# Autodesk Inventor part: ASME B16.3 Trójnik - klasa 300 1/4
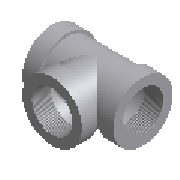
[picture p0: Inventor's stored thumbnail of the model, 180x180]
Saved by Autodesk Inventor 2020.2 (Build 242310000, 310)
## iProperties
Manager: www.cadconsulting.pl
Company: Fabian Stasiak CAD Consulting
Created: 2016-02
Part Number: ASME B16.3 Trójnik - klasa 300 1/4
Material: Żelazo, ciągliwe
Description: Trójnik
Document SubType Name: Modeling
Standard: ASME B16.3
Designer: F.Stasiak
Standard Revision: 2011
Standards Organization: ANSI
Language: pl-PL
Size Designation: 1/4
Categories: <MemberInstance><Categories><Category DisplayName="Rury cienko- i grubościenne" InternalName="4347fa0f-2144-441d-94cd-e3e15c92b736" Mnemonic="TUBEANDPIPE"><Cate
Density: 7.15 g/cm^3
Appearance: Częściowo polerowana
Catalog Web Link: www.expertbooks.pl
NAME: PIPING: ASME B16.3 Tee - Class 300
DATA: <meta><inlinegroups number="1" deflen="4.7752"></inlinegroups><connections number="3"></connections><angles><a>3.14159265358979</a><a>1.5707963267949</a></angle
IsCustomPart: 0
Author: F.Stasiak
Subject: Zbiór ćwiczeń. Autodesk Inventor 2020. Kurs Professional
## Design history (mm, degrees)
sketch "Sketch1"
  geometry: L1 (0, 11.811)-(9.652, 11.811); L2 (9.652, 11.811)-(9.652, 10.922); L3 (38.1, 10.922)-(38.1, 11.811); L4 (38.1, 11.811)-(47.752, 11.811); L5 (47.752, 11.811)-(47.752, 5.679); L6 (47.752, 5.679)-(47.752, 0); L7 (47.752, 0)-(0, 0); L8 (0, 0)-(0, 5.679); L9 (0, 5.679)-(10.922, 5.338); L10 (10.922, 5.338)-(10.922, 7.366); L11 (47.752, 5.679)-(36.83, 5.338); L12 (36.83, 5.338)-(36.83, 7.366); L13 (0, 5.679)-(0, 11.811); L14 (9.652, 11.811)-(23.876, 11.811); L15 (23.876, 11.811)-(38.1, 11.811); L16 (23.876, 11.811)-(23.876, 0); L17 (9.652, 10.922)-(23.876, 10.922); L18 (23.876, 10.922)-(38.1, 10.922); L19 (10.922, 7.366)-(23.876, 7.366); L20 (23.876, 7.366)-(36.83, 7.366)
  constraints: 40 end point, 5 perpendicular, 4 collinear, 3 parallel, 2 point on line, 1 horizontal, 1 midpoint, 8 other
  dimensions: "d0" = 11.35863 diameter of L8.end L7 (= MD); "d1" = 23.622 diameter of L1 L7 (= H); "d2" = 9.652 distance of L1.start L1.end (= E1); "d3" = 23.876 distance of L14.end L1.start (= A); "d4" = 10.922 horizontal distance of L9.end L8.end (= B); "d5" = 14.732 diameter of L19 L7 (= F1); "d6" = 3.556 distance between parallel lines of L19 L17 (= G); "d7" = 1.78991 deg angle of L7 L9
revolve "Revolve1" stored, may be unused: angle "d11" = 90 deg
workplane "Work Plane1"
sketch "Sketch2"
  geometry: L1 (0, 11.811)-(0, -11.811) reference; L2 (47.752, 11.811)-(47.752, -11.811) reference; L3 (47.752, 5.679)-(47.752, -5.679) reference; L4 (0, 0)-(47.752, 0); C1 r 5.679 at (23.876, 0); C2 r 10.922 at (23.876, 0); C3 r 11.811 at (23.876, 0)
  constraints: 3 centre point, 3 midpoint, 2 coincident, 2 concentric, 2 end point
  dimensions: "d9" = 23.622 diameter of C3 (= H); "d10" = 21.844 diameter of C2 (= F1 + 2 x G); "d12" = 11.35863 diameter of C1 (= MD)
  node "Projected Loop1"
extrude "Extrude1" join sketch "Sketch2" taper "d13" = 0 deg; stored distance "d16" = 25.4
extrude "Extrude2" cut sketch "Sketch2" distance "d14" = 23.876 (= A); taper "d15" = -1.78991 deg
extrude "Extrude3" join sketch "Sketch2" distance "d17" = 9.652 (= E1); taper "d18" = 0 deg
sketch "Sketch4"
  geometry: L1 (47.752, 11.811)-(47.752, -11.811) reference; L2 (0, 11.811)-(0, -11.811) reference; L3 (47.752, 0)-(0, 0); C1 r 7.366 at (23.876, 0)
  constraints: 3 midpoint, 2 end point, 1 centre point
  dimensions: "d19" = 14.732 diameter of C1 (= F1)
extrude "Extrude4" cut sketch "Sketch4" distance "d20" = 12.954 (= A - B); taper "d21" = 0 deg
workaxis "Work Axis1"
workpoint "Work Point1"
workpoint "Work Point2"
workaxis "Work Axis2"
workpoint "Work Point3"
workpoint "Work Point4"
workaxis "Work Axis3"
workpoint "Work Point5"
workpoint "Work Point6"
body "Solid1"
feature "Gwint1" dims "d32" = 25.4, "d33" = 0
feature "Gwint2" dims "d34" = 25.4, "d35" = 0
feature "Gwint3" dims "d36" = 25.4, "d37" = 0
other parameters: "A" = 23.876 [user parameter; used in 4 equation terms], "B" = 10.922 [user parameter; used in 2 equation terms], "E1" = 9.652 [user parameter; used in 2 equation terms], "F1" = 14.732 [user parameter; used in 3 equation terms], "G" = 3.556 [user parameter; used in 2 equation terms], "H" = 23.622 [user parameter; used in 2 equation terms], "MD" = 11.35863 [user parameter; used in 2 equation terms], "d8" = 23.876 (= A), "Size_Designation" = 2.5 [user parameter]
